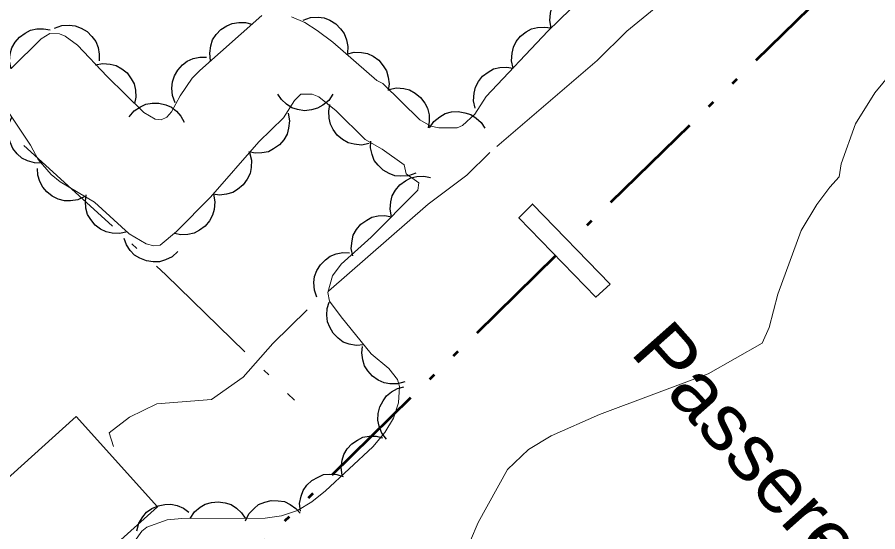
# Model space of a CAD drawing. Extents: x 386081 to 389416, y 5130568 to 5134082.
# Drawn here: x 387289.32 to 387336.1, y 5132090.78 to 5132118.78 of the extents above; entities that cross this region are included whole.
import ezdxf

# ---------------------------------------------------------------- set-up
doc = ezdxf.new("R2010")
doc.units = 0
doc.header["$LTSCALE"] = 1.2
for name, pattern in [('DASH_DOUBLE_DOT', [9.2, 5, -1.2, 0.3, -1.2, 0.3, -1.2]), ('DOT_DASHED', [7.7, 5, -1.2, 0.3, -1.2]), ('LONG_DASHED', [7.5, 6, -1.5])]:
    doc.linetypes.add(name, pattern=pattern)
for name, color, linetype, lineweight in [('2', 7, 'Continuous', 13), ('26', 7, 'Continuous', 35), ('31', 7, 'Continuous', 70), ('4', 7, 'DASH_DOUBLE_DOT', 53), ('41', 7, 'DOT_DASHED', 25), ('44', 7, 'Continuous', 25)]:
    doc.layers.add(name, color=color, linetype=linetype, lineweight=lineweight)

msp = doc.modelspace()

# ---------------------------------------------------------------- linework, layer by layer
at = {"layer": '2', "linetype": 'LONG_DASHED'}
for points in [[(387336.86, 5132129.5), (387331.76, 5132124.48), (387328.91, 5132122.4), (387325.69, 5132120.45), (387323.95, 5132119.23), (387322.46, 5132118.01), (387320.85, 5132116.42), (387315.01, 5132111.41), (387313.77, 5132110.19), (387311.66, 5132108.6), (387305.08, 5132102.86), (387303.22, 5132101.03), (387301.6, 5132099.19), (387299.87, 5132097.97), (387296.91, 5132097.74), (387295.42, 5132097.01), (387294.31, 5132096.16), (387294.55, 5132095.42)], [(387313.96, 5132090.3), (387314.38, 5132091.29), (387315.98, 5132094.17), (387317.11, 5132095.25), (387318.35, 5132096), (387320.98, 5132097.17), (387326.88, 5132099.37), (387329.81, 5132101.05), (387330.2, 5132101.9), (387330.67, 5132103.7), (387331.93, 5132107.17), (387332.79, 5132108.59), (387333.49, 5132109.53), (387334, 5132110.09), (387334.12, 5132110.8), (387334.9, 5132112.98), (387335.94, 5132114.66), (387337.45, 5132116.49)]]:
    msp.add_lwpolyline(points, dxfattribs=at)
at = {"layer": '26'}
msp.add_lwpolyline([(387321.55, 5132104.26), (387317.33, 5132108.61), (387316.59, 5132107.86), (387320.77, 5132103.55)], close=True, dxfattribs=at)
at = {"layer": '31', "lineweight": 35}
msp.add_lwpolyline([(387292.52, 5132097.06), (387286.7, 5132091.81), (387291.12, 5132086.9), (387296.95, 5132092.14)], close=True, dxfattribs=at)
at = {"layer": '4'}
msp.add_line((387341.66, 5132128.32), (387319.35, 5132106.53), dxfattribs=at)
msp.add_lwpolyline([(387318.59, 5132105.79), (387271.28, 5132059.47), (387242.97, 5132030.44), (387221.09, 5132009.79)], dxfattribs=at)
at = {"layer": '41'}
msp.add_lwpolyline([(387270.69, 5132130.26), (387282.94, 5132118.13), (387290.05, 5132111.45), (387297.4, 5132104.76), (387304.39, 5132097.95)], dxfattribs=at)
at = {"layer": '44', "linetype": 'DOT_DASHED', "lineweight": 13}
for points in [[(387304.23, 5132118.8), (387304.96, 5132118.48), (387305.63, 5132118.05), (387306.47, 5132117.42), (387308.87, 5132115.33), (387309.2, 5132115.16), (387311.21, 5132113.19), (387311.8, 5132112.84), (387312.23, 5132112.76), (387313.24, 5132112.75), (387313.53, 5132112.88), (387314.19, 5132113.5), (387314.82, 5132114.46), (387318.17, 5132118.01), (387320.58, 5132120.38)], [(387288.99, 5132115.98), (387290.61, 5132117.59), (387291.08, 5132117.88), (387291.61, 5132117.87), (387291.93, 5132117.75), (387292.6, 5132117.26), (387294.21, 5132115.54), (387296.2, 5132113.59), (387296.82, 5132113.22), (387297.14, 5132113.19), (387297.45, 5132113.34), (387297.7, 5132113.63), (387298.17, 5132114.5), (387298.83, 5132115.46), (387299.24, 5132115.88), (387302.62, 5132118.87)], [(387295.7, 5132090.25), (387296.09, 5132090.82), (387296.37, 5132091.04), (387297.47, 5132091.43), (387298.27, 5132091.51), (387302.8, 5132091.53), (387303.69, 5132091.65), (387304.56, 5132091.94), (387305.33, 5132092.41), (387306.07, 5132093.01), (387308.65, 5132095.4), (387309.3, 5132096.18), (387309.77, 5132096.96), (387310.05, 5132097.8), (387310.1, 5132098.69), (387309.99, 5132099.07), (387309.52, 5132099.67), (387308.56, 5132100.47), (387306.93, 5132102.47), (387306.3, 5132103.33), (387306.21, 5132103.79), (387306.46, 5132104.7), (387306.93, 5132105.34), (387308.56, 5132106.8), (387311.1, 5132109.37), (387311.15, 5132109.76), (387310.46, 5132110.26), (387310.35, 5132110.74), (387309.16, 5132111.59), (387308.23, 5132112.12), (387306.65, 5132113.69), (387305.71, 5132114.45), (387305.36, 5132114.59), (387304.74, 5132114.59), (387304.4, 5132114.25), (387303.79, 5132113.3), (387302.45, 5132111.99), (387299.82, 5132108.98), (387297.98, 5132107.12), (387297.08, 5132106.38), (387296.74, 5132106.34), (387296.33, 5132106.44)], [(387296.33, 5132106.44), (387295.41, 5132106.99), (387293.52, 5132108.71), (387291.65, 5132109.82), (387291.16, 5132110.21), (387290.46, 5132111.03), (387290.03, 5132111.82), (387288.7, 5132113.82)]]:
    msp.add_lwpolyline(points, dxfattribs=at)
at = {"layer": '44'}
for points in [[(387318.34, 5132118.18), (387318.27, 5132118.59), (387318.31, 5132119), (387318.39, 5132119.32), (387318.57, 5132119.62), (387318.81, 5132119.9), (387319.13, 5132120.12), (387319.41, 5132120.28), (387319.76, 5132120.34), (387320.13, 5132120.36), (387320.48, 5132120.28)], [(387304.87, 5132118.62), (387305.26, 5132118.76), (387305.67, 5132118.77), (387306, 5132118.74), (387306.32, 5132118.61), (387306.64, 5132118.41), (387306.9, 5132118.14), (387307.1, 5132117.88), (387307.22, 5132117.55), (387307.29, 5132117.18), (387307.27, 5132116.82)], [(387288.98, 5132115.97), (387288.9, 5132116.38), (387288.94, 5132116.78), (387289.02, 5132117.1), (387289.2, 5132117.41), (387289.44, 5132117.69), (387289.75, 5132117.91), (387290.04, 5132118.07), (387290.38, 5132118.14), (387290.75, 5132118.15), (387291.11, 5132118.08)], [(387291.35, 5132118.18), (387291.74, 5132118.32), (387292.14, 5132118.34), (387292.47, 5132118.31), (387292.8, 5132118.18), (387293.12, 5132117.99), (387293.38, 5132117.72), (387293.59, 5132117.46), (387293.71, 5132117.13), (387293.78, 5132116.77), (387293.77, 5132116.41)], [(387299.83, 5132116.4), (387299.78, 5132116.82), (387299.85, 5132117.22), (387299.94, 5132117.54), (387300.14, 5132117.83), (387300.39, 5132118.1), (387300.72, 5132118.3), (387301.01, 5132118.44), (387301.36, 5132118.49), (387301.73, 5132118.48), (387302.08, 5132118.39)], [(387316.28, 5132116.01), (387316.19, 5132116.41), (387316.22, 5132116.82), (387316.29, 5132117.14), (387316.45, 5132117.45), (387316.68, 5132117.74), (387316.99, 5132117.97), (387317.27, 5132118.14), (387317.61, 5132118.22), (387317.98, 5132118.24), (387318.34, 5132118.19)], [(387307.22, 5132116.76), (387307.63, 5132116.87), (387308.03, 5132116.86), (387308.36, 5132116.8), (387308.67, 5132116.65), (387308.97, 5132116.43), (387309.22, 5132116.13), (387309.39, 5132115.86), (387309.49, 5132115.52), (387309.53, 5132115.15), (387309.48, 5132114.79)], [(387293.56, 5132116.18), (387293.97, 5132116.26), (387294.37, 5132116.22), (387294.7, 5132116.15), (387295, 5132115.97), (387295.29, 5132115.74), (387295.51, 5132115.43), (387295.67, 5132115.15), (387295.75, 5132114.8), (387295.77, 5132114.43), (387295.7, 5132114.08)], [(387297.91, 5132114.12), (387297.76, 5132114.51), (387297.73, 5132114.92), (387297.75, 5132115.25), (387297.86, 5132115.58), (387298.05, 5132115.9), (387298.31, 5132116.18), (387298.56, 5132116.39), (387298.89, 5132116.52), (387299.25, 5132116.6), (387299.61, 5132116.6)], [(387314.22, 5132113.82), (387314.13, 5132114.23), (387314.16, 5132114.64), (387314.23, 5132114.96), (387314.4, 5132115.27), (387314.62, 5132115.56), (387314.93, 5132115.79), (387315.21, 5132115.96), (387315.55, 5132116.04), (387315.92, 5132116.06), (387316.28, 5132116.01)], [(387309.52, 5132114.85), (387309.93, 5132114.93), (387310.33, 5132114.89), (387310.65, 5132114.82), (387310.96, 5132114.65), (387311.24, 5132114.41), (387311.47, 5132114.1), (387311.63, 5132113.82), (387311.71, 5132113.47), (387311.72, 5132113.1), (387311.66, 5132112.75)], [(387306.48, 5132114.59), (387306.25, 5132114.24), (387305.93, 5132113.99), (387305.65, 5132113.82), (387305.31, 5132113.73), (387304.94, 5132113.69), (387304.56, 5132113.76), (387304.25, 5132113.85), (387303.96, 5132114.04), (387303.68, 5132114.29), (387303.48, 5132114.59)], [(387295.41, 5132113.35), (387295.67, 5132113.68), (387296.01, 5132113.9), (387296.31, 5132114.05), (387296.66, 5132114.1), (387297.02, 5132114.1), (387297.4, 5132114), (387297.7, 5132113.88), (387297.97, 5132113.66), (387298.22, 5132113.39), (387298.39, 5132113.07)], [(387308.45, 5132111.9), (387308.04, 5132111.82), (387307.63, 5132111.86), (387307.31, 5132111.94), (387307.01, 5132112.12), (387306.72, 5132112.35), (387306.5, 5132112.66), (387306.34, 5132112.95), (387306.27, 5132113.29), (387306.25, 5132113.66), (387306.32, 5132114.02)], [(387304.04, 5132113.55), (387304.12, 5132113.13), (387304.07, 5132112.73), (387303.99, 5132112.41), (387303.81, 5132112.11), (387303.57, 5132111.83), (387303.25, 5132111.61), (387302.97, 5132111.45), (387302.62, 5132111.39), (387302.25, 5132111.38), (387301.9, 5132111.45)], [(387311.74, 5132112.76), (387311.97, 5132113.11), (387312.29, 5132113.36), (387312.58, 5132113.53), (387312.92, 5132113.62), (387313.29, 5132113.65), (387313.66, 5132113.58), (387313.98, 5132113.49), (387314.27, 5132113.29), (387314.54, 5132113.04), (387314.74, 5132112.74)], [(387290.68, 5132110.84), (387290.26, 5132110.85), (387289.87, 5132110.97), (387289.57, 5132111.11), (387289.31, 5132111.34), (387289.08, 5132111.63), (387288.93, 5132111.98), (387288.82, 5132112.29), (387288.82, 5132112.64), (387288.88, 5132113.01), (387289.02, 5132113.34)], [(387310.98, 5132110.29), (387310.59, 5132110.14), (387310.18, 5132110.12), (387309.85, 5132110.14), (387309.53, 5132110.27), (387309.21, 5132110.46), (387308.94, 5132110.73), (387308.73, 5132110.98), (387308.61, 5132111.31), (387308.53, 5132111.67), (387308.54, 5132112.03)], [(387301.94, 5132111.41), (387302.05, 5132111), (387302.03, 5132110.6), (387301.98, 5132110.27), (387301.82, 5132109.96), (387301.6, 5132109.66), (387301.3, 5132109.41), (387301.03, 5132109.24), (387300.69, 5132109.14), (387300.32, 5132109.1), (387299.97, 5132109.15)], [(387293, 5132109.02), (387292.62, 5132108.84), (387292.22, 5132108.78), (387291.89, 5132108.78), (387291.55, 5132108.87), (387291.22, 5132109.03), (387290.93, 5132109.28), (387290.7, 5132109.52), (387290.55, 5132109.83), (387290.44, 5132110.19), (387290.42, 5132110.55)], [(387309.67, 5132107.92), (387309.59, 5132108.33), (387309.63, 5132108.73), (387309.7, 5132109.06), (387309.88, 5132109.36), (387310.11, 5132109.65), (387310.42, 5132109.87), (387310.71, 5132110.03), (387311.05, 5132110.1), (387311.42, 5132110.12), (387311.78, 5132110.05)], [(387295.29, 5132107.1), (387294.89, 5132107), (387294.48, 5132107.02), (387294.16, 5132107.09), (387293.84, 5132107.25), (387293.55, 5132107.47), (387293.31, 5132107.77), (387293.14, 5132108.05), (387293.05, 5132108.39), (387293.02, 5132108.76), (387293.07, 5132109.12)], [(387299.98, 5132109.14), (387300.06, 5132108.73), (387300.02, 5132108.32), (387299.94, 5132108), (387299.77, 5132107.7), (387299.53, 5132107.41), (387299.22, 5132107.19), (387298.94, 5132107.03), (387298.59, 5132106.96), (387298.22, 5132106.94), (387297.87, 5132107.01)], [(387307.56, 5132105.79), (387307.48, 5132106.2), (387307.52, 5132106.6), (387307.59, 5132106.92), (387307.77, 5132107.23), (387308, 5132107.51), (387308.32, 5132107.74), (387308.6, 5132107.9), (387308.94, 5132107.97), (387309.31, 5132107.99), (387309.67, 5132107.92)], [(387298.05, 5132106.02), (387297.74, 5132105.74), (387297.37, 5132105.57), (387297.06, 5132105.47), (387296.7, 5132105.46), (387296.34, 5132105.52), (387295.99, 5132105.67), (387295.7, 5132105.83), (387295.46, 5132106.09), (387295.26, 5132106.39), (387295.13, 5132106.73)], [(387305.61, 5132103.54), (387305.47, 5132103.93), (387305.45, 5132104.34), (387305.48, 5132104.67), (387305.6, 5132104.99), (387305.8, 5132105.31), (387306.07, 5132105.58), (387306.33, 5132105.78), (387306.66, 5132105.9), (387307.02, 5132105.97), (387307.38, 5132105.96)], [(387308.17, 5132100.95), (387307.75, 5132100.91), (387307.36, 5132100.99), (387307.04, 5132101.1), (387306.76, 5132101.31), (387306.5, 5132101.58), (387306.31, 5132101.91), (387306.18, 5132102.21), (387306.15, 5132102.56), (387306.17, 5132102.93), (387306.28, 5132103.27)], [(387310.39, 5132098.94), (387309.99, 5132098.83), (387309.58, 5132098.83), (387309.26, 5132098.88), (387308.94, 5132099.03), (387308.63, 5132099.24), (387308.38, 5132099.53), (387308.2, 5132099.8), (387308.1, 5132100.14), (387308.05, 5132100.51), (387308.09, 5132100.86)], [(387309.39, 5132095.82), (387309.14, 5132096.15), (387308.99, 5132096.53), (387308.92, 5132096.86), (387308.94, 5132097.21), (387309.03, 5132097.57), (387309.21, 5132097.9), (387309.39, 5132098.17), (387309.67, 5132098.39), (387309.99, 5132098.57), (387310.34, 5132098.67)], [(387306.98, 5132093.86), (387306.92, 5132094.27), (387306.98, 5132094.67), (387307.07, 5132094.99), (387307.25, 5132095.29), (387307.5, 5132095.56), (387307.82, 5132095.77), (387308.11, 5132095.92), (387308.46, 5132095.98), (387308.83, 5132095.98), (387309.18, 5132095.89)], [(387304.71, 5132091.9), (387304.67, 5132092.32), (387304.75, 5132092.72), (387304.86, 5132093.03), (387305.07, 5132093.31), (387305.34, 5132093.57), (387305.67, 5132093.76), (387305.97, 5132093.89), (387306.32, 5132093.92), (387306.69, 5132093.9), (387307.04, 5132093.79)], [(387298.71, 5132091.51), (387298.95, 5132091.86), (387299.26, 5132092.12), (387299.54, 5132092.29), (387299.88, 5132092.38), (387300.25, 5132092.41), (387300.63, 5132092.35), (387300.94, 5132092.27), (387301.24, 5132092.07), (387301.51, 5132091.82), (387301.71, 5132091.53)], [(387301.72, 5132091.38), (387301.91, 5132091.76), (387302.19, 5132092.05), (387302.44, 5132092.26), (387302.77, 5132092.4), (387303.13, 5132092.48), (387303.51, 5132092.47), (387303.84, 5132092.42), (387304.15, 5132092.27), (387304.46, 5132092.05), (387304.7, 5132091.79)], [(387295.82, 5132090.84), (387295.92, 5132091.25), (387296.14, 5132091.6), (387296.34, 5132091.85), (387296.63, 5132092.05), (387296.97, 5132092.2), (387297.35, 5132092.27), (387297.67, 5132092.29), (387298.02, 5132092.21), (387298.36, 5132092.06), (387298.65, 5132091.85)]]:
    msp.add_lwpolyline(points, dxfattribs=at)

# ---------------------------------------------------------------- texts
at = {"layer": '26', "width": 1.1}
msp.add_text('Passerelle', height=3, rotation=311.552, dxfattribs=at).set_placement((387322.58, 5132100.52))

doc.saveas('drawing.dxf')
